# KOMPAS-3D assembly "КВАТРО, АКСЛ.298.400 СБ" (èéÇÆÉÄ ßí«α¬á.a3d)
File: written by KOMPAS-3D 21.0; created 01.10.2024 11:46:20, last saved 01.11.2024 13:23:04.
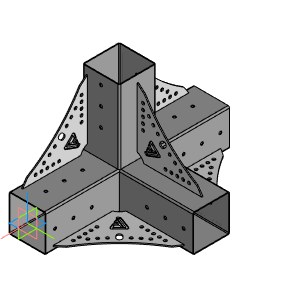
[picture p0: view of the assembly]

Document properties: Полное имя файла: C:\Users\79253\YandexDisk\Соединения бруса\Соединения бруса\КВАТРО\КВАТРО сборка.a3d; Автор: Алексей Бочаров

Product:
- Part/product: КВАТРО  | designation АКСЛ.298.400 СБ
    Масса: 6.994498
    Форматы листов документа: A4
    source file: АКСЛ.298.400 - КВАТРО.spw
  - Component [detail]: Профиль L = 500 мм  | designation АКСЛ.298.402  | pos. 3  | Масса: 3.029613; source file: Профиль L = 500 мм.cdw, Профиль L = 500 мм.m3d
  - Component [detail]: Профиль L = 200 мм  | designation АКСЛ.298.401  | qty 2  | pos. 2  | Масса: 1.210897; source file: Профиль L = 200 мм.cdw, Профиль L = 200 мм.m3d
  - Component [assembly]: Перемычка  | designation АКСЛ.298.201  | qty 5  | pos. 1  | Масса: 0.308618; source file: ..\Перемычка.stp

Referenced files in C:\Users\79253\YandexDisk\Соединения бруса\Соединения бруса\КВАТРО\: Профиль L = 500 мм.m3d, Профиль L = 200 мм.m3d
Referenced files: АКСЛ.298.400 СБ>Деталь (локальная).m3d
Referenced files in C:\Users\79253\YandexDisk\Соединения бруса\Соединения бруса\: Перемычка.stp
Referenced files in C:\Users\Алексей Бочаров\YandexDisk\Соединения бруса\Соединения бруса\КВАТРО\: Профиль L = 200 мм.m3d
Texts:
  АКСЛ.298.400 СБ
  АКСЛ.298.402 Профиль L = 500 мм
  АКСЛ.298.401 Профиль L = 200 мм (1)
  АКСЛ.298.201 Перемычка (1)
  АКСЛ.298.201 Перемычка (2)
  АКСЛ.298.201 Перемычка (3)
  АКСЛ.298.201 Перемычка (4)
  АКСЛ.298.201 Перемычка (5)
  АКСЛ.298.401 Профиль L = 200 мм (2)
